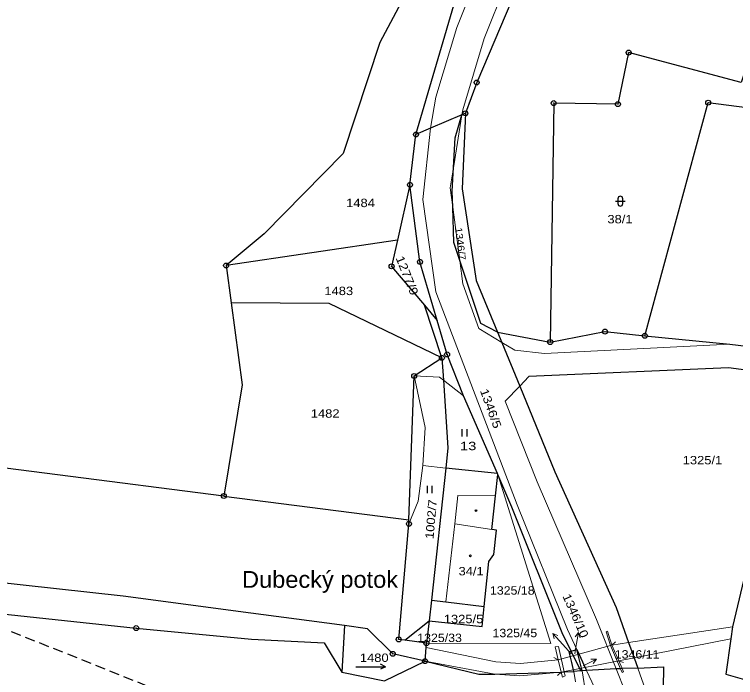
# Model space of a CAD drawing. Extents: x -872229 to -869198, y -1075981 to -1074329.
# Drawn here: x -871207 to -871061.1, y -1075218 to -1075083.8 of the extents above; entities that cross this region are included whole.
import ezdxf
from ezdxf.enums import TextEntityAlignment as Align

# ---------------------------------------------------------------- set-up
doc = ezdxf.new("R2010")
doc.units = 0
doc.header["$LTSCALE"] = 0.68
doc.linetypes.add('MEDIUM_DASHED', pattern=[4.5, 3, -1.5])
for name, color, linetype, lineweight in [('1', 7, 'Continuous', 25), ('3', 7, 'Continuous', 25), ('4', 7, 'Continuous', 13), ('5', 7, 'Continuous', 25), ('6', 7, 'Continuous', 25), ('7', 7, 'Continuous', 13), ('8', 7, 'Continuous', 25)]:
    doc.layers.add(name, color=color, linetype=linetype, lineweight=lineweight)
doc.layers.add('2', color=7, linetype='Continuous')

msp = doc.modelspace()

# ---------------------------------------------------------------- linework, layer by layer
at = {"layer": '1'}
for p, q in [((-871126.95, -1075118.28), (-871125.74, -1075108.09)), ((-871124.04, -1075142.67), (-871121.45, -1075145.75)), ((-871120.49, -1075153.3), (-871124.04, -1075142.67)), ((-871122.61, -1075202.33), (-871123.06, -1075206.55)), ((-871128.02, -1075210.46), (-871123.06, -1075206.55)), ((-871123.06, -1075206.55), (-871123.63, -1075211.06)), ((-871092.41, -1075216.68), (-871094.34, -1075212.69)), ((-871092.1, -1075216.66), (-871093.16, -1075212.36)), ((-871091.2, -1075216.61), (-871092.1, -1075216.66))]:
    msp.add_line(p, q, dxfattribs=at)
for points in [[(-871125.74, -1075108.09), (-871117.37, -1075079.56), (-871098, -1075028.09)], [(-871096.99, -1075058.79), (-871113.45, -1075097.58), (-871115.74, -1075103.81)], [(-871124.45, -1075073.24), (-871133.02, -1075089.5), (-871140.45, -1075111.97), (-871156.44, -1075128.18), (-871164.16, -1075134.61)], [(-871054.49, -1075088.37), (-871056.71, -1075087.82), (-871059.95, -1075097.6), (-871082.7, -1075091.52), (-871084.87, -1075101.96), (-871097.87, -1075101.74), (-871098.57, -1075150.11)], [(-871079.42, -1075148.83), (-871066.59, -1075101.65), (-871036.85, -1075105.44)], [(-871116.43, -1075104.1), (-871122.77, -1075106.82), (-871125.74, -1075108.09)], [(-871109.24, -1075148.09), (-871112.62, -1075146.34), (-871116.89, -1075133.59), (-871118.1, -1075129.96), (-871118.31, -1075122.79), (-871118.41, -1075119.59), (-871117.78, -1075108.8), (-871116.43, -1075104.1)], [(-871115.74, -1075103.81), (-871116.41, -1075104.1), (-871116.43, -1075104.1)], [(-871115.74, -1075103.81), (-871116.38, -1075119.08), (-871113.54, -1075137.64), (-871109.24, -1075148.09), (-871098.57, -1075150.11)], [(-871079.42, -1075148.83), (-871062.25, -1075150.52), (-871046.01, -1075152.47), (-871037.58, -1075154.42), (-871036.85, -1075105.44)], [(-871121.45, -1075145.75), (-871124.93, -1075133.89), (-871126.95, -1075118.28), (-871129.49, -1075129.5)], [(-871129.49, -1075129.5), (-871164.16, -1075134.61), (-871163.14, -1075142.16)], [(-871129.49, -1075129.5), (-871130.67, -1075134.78), (-871124.04, -1075142.67)], [(-871163.14, -1075142.16), (-871160.9, -1075158.75), (-871164.62, -1075181.27), (-871127.17, -1075186.06)], [(-871120.49, -1075153.3), (-871143.29, -1075142.31), (-871163.14, -1075142.16)], [(-871109.26, -1075176.73), (-871116.14, -1075160.96), (-871119.44, -1075152.61), (-871121.45, -1075145.75)], [(-871098.57, -1075150.11), (-871087.49, -1075147.99), (-871079.42, -1075148.83)], [(-871164.62, -1075181.27), (-871265.65, -1075168.37), (-871373.25, -1075154.62), (-871412.02, -1075149.67), (-871424.63, -1075148.05)], [(-871109.24, -1075148.09), (-871108.38, -1075150.17), (-871104.75, -1075159)], [(-871127.17, -1075186.06), (-871126.1, -1075156.97), (-871120.49, -1075153.3)], [(-871120.49, -1075153.3), (-871120.19, -1075157.85), (-871119.29, -1075171.49), (-871119.73, -1075175.61)], [(-870920.27, -1075200.54), (-870931.8, -1075197.32), (-870942.08, -1075192.95), (-870971.72, -1075177.36), (-871005.41, -1075167.04), (-871047.1, -1075157.35), (-871062.52, -1075155.35), (-871102.88, -1075157.06), (-871104.75, -1075159), (-871097.61, -1075176.34), (-871085.24, -1075203.86)], [(-871109.2, -1075176.94), (-871109.26, -1075176.73), (-871119.73, -1075175.61), (-871122.61, -1075202.33), (-871119.69, -1075202.71), (-871111.95, -1075203.66)], [(-871111.95, -1075203.66), (-871110.99, -1075194.53), (-871109.95, -1075193.13), (-871109.41, -1075188.17), (-871110.36, -1075188.06), (-871109.64, -1075181.21), (-871109.2, -1075176.94)], [(-871094.34, -1075212.69), (-871096.14, -1075208.96), (-871106.32, -1075183.51), (-871109.2, -1075176.94)], [(-871001.53, -1075179.18), (-871004.71, -1075177.87), (-871056.06, -1075184.2), (-871061.68, -1075207.72), (-871062.03, -1075210.19), (-871063.04, -1075217.35), (-871059.26, -1075218.39), (-871047.62, -1075220.14), (-871017.06, -1075226.57)], [(-871128.02, -1075210.46), (-871129.23, -1075210.29), (-871127.16, -1075186.91), (-871127.17, -1075186.06)], [(-871140.23, -1075207.5), (-871147.35, -1075206.55), (-871159.14, -1075204.95), (-871185.02, -1075201.57), (-871218.75, -1075197.81)], [(-871219.01, -1075204.11), (-871182.37, -1075208), (-871159.03, -1075210.24), (-871144.33, -1075210.97), (-871140.73, -1075216.95)], [(-871123.06, -1075206.55), (-871112.34, -1075207.69), (-871111.95, -1075203.66)], [(-871085.24, -1075203.86), (-871082.7, -1075210.94), (-871081.59, -1075214.04), (-871080.85, -1075216.08)], [(-871123.91, -1075214.69), (-871130.44, -1075213.21), (-871135.53, -1075208.13), (-871140.23, -1075207.5), (-871140.73, -1075216.95)], [(-871123.91, -1075214.69), (-871123.7, -1075211.96), (-871123.63, -1075211.06), (-871128.02, -1075210.46)], [(-871094.22, -1075214.97), (-871094.76, -1075212.8), (-871094.34, -1075212.69)], [(-871094.34, -1075212.69), (-871093.16, -1075212.36), (-871091.2, -1075216.61)], [(-871140.73, -1075216.95), (-871132.14, -1075218.66), (-871123.91, -1075214.69)], [(-871123.91, -1075214.69), (-871112.99, -1075217.35), (-871109.77, -1075217.3), (-871096.36, -1075216.91)], [(-871096.36, -1075216.91), (-871095.74, -1075216.87), (-871093.8, -1075216.76), (-871094.22, -1075214.97)], [(-871080.85, -1075216.08), (-871084.02, -1075216.21), (-871084.34, -1075216.22), (-871085.21, -1075216.27), (-871091.2, -1075216.61)], [(-871080.85, -1075216.08), (-871075.68, -1075215.86), (-871075.69, -1075220.23), (-871047.62, -1075220.14)], [(-871092.1, -1075216.66), (-871092.41, -1075216.68), (-871093.8, -1075216.76)]]:
    msp.add_lwpolyline(points, dxfattribs=at)
at = {"layer": '3'}
for p, q in [((-871085.391, -1075121.591), (-871083.389, -1075121.591)), ((-871084.891, -1075121.091), (-871084.891, -1075122.092)), ((-871083.889, -1075122.092), (-871083.889, -1075121.091)), ((-871116.411, -1075169.23), (-871116.411, -1075167.73)), ((-871115.41, -1075169.23), (-871115.41, -1075167.73)), ((-871123.431, -1075180.69), (-871123.431, -1075179.19)), ((-871122.43, -1075180.69), (-871122.43, -1075179.19)), ((-871131.933, -1075215.829), (-871132.91, -1075216.33))]:
    msp.add_line(p, q, dxfattribs=at)
msp.add_lwpolyline([(-871137.933, -1075215.829), (-871131.933, -1075215.829), (-871132.91, -1075215.327)], dxfattribs=at)
for centre, start, end in [((-871084.39, -1075121.0909), 0, 180), ((-871084.39, -1075122.0909), 180, 359.98789)]:
    msp.add_arc(centre, 0.5, start, end, dxfattribs=at)
at = {"layer": '4'}
for p, q in [((-871121.71, -1075100.52), (-871117.44, -1075086.44)), ((-871122.77, -1075106.82), (-871121.71, -1075100.52)), ((-871124.35, -1075121.24), (-871122.77, -1075106.82)), ((-871118.83, -1075118.87), (-871118.11, -1075114.44)), ((-871118.83, -1075118.87), (-871118.31, -1075122.79)), ((-871124.35, -1075121.24), (-871121.72, -1075139.93)), ((-871116.26, -1075138.33), (-871113.05, -1075147.37)), ((-871121.72, -1075139.93), (-871105.23, -1075183.06)), ((-871113.05, -1075147.37), (-871108.38, -1075150.17)), ((-871108.38, -1075150.17), (-871105.73, -1075151.76)), ((-871099.7, -1075152.44), (-871062.25, -1075150.52)), ((-871105.73, -1075151.76), (-871099.7, -1075152.44)), ((-871126.1, -1075156.97), (-871123.88, -1075167.38)), ((-871126.1, -1075156.97), (-871120.99, -1075157.24)), ((-871107.69, -1075162.06), (-871104.75, -1075159)), ((-871107.69, -1075162.06), (-871101.22, -1075178.38)), ((-871124.35, -1075175.12), (-871123.88, -1075167.38)), ((-871125.31, -1075182.31), (-871124.35, -1075175.12)), ((-871124.35, -1075175.12), (-871119.73, -1075175.61)), ((-871109.2, -1075176.94), (-871098.43, -1075211.1)), ((-871101.22, -1075178.38), (-871089.2, -1075206.25)), ((-871127.16, -1075186.91), (-871125.31, -1075182.31)), ((-871105.23, -1075183.06), (-871095.06, -1075208.25)), ((-871119.69, -1075202.71), (-871117.87, -1075186.88)), ((-871117.87, -1075186.88), (-871110.36, -1075188.06)), ((-871089.2, -1075206.25), (-871085.21, -1075216.27)), ((-871082.7, -1075210.94), (-871061.68, -1075207.72)), ((-871095.06, -1075208.25), (-871093.16, -1075212.36)), ((-871087.28, -1075208.73), (-871086.99, -1075208.64)), ((-871087.28, -1075208.73), (-871086.38, -1075211.55)), ((-871086.99, -1075208.64), (-871086.09, -1075211.46)), ((-871085.382, -1075210.753), (-871086.089, -1075211.46)), ((-871081.59, -1075214.04), (-871062.03, -1075210.19)), ((-871123.7, -1075211.96), (-871109.59, -1075214.81)), ((-871123.63, -1075211.06), (-871098.43, -1075211.1)), ((-871097.55, -1075211.81), (-871096.93, -1075211.74)), ((-871096.93, -1075211.74), (-871095.74, -1075216.87)), ((-871086.38, -1075211.55), (-871084.34, -1075216.22)), ((-871086.09, -1075211.46), (-871082.7, -1075210.94)), ((-871086.09, -1075211.46), (-871084.69, -1075214.65)), ((-871123.91, -1075214.69), (-871109.77, -1075217.3)), ((-871109.59, -1075214.81), (-871104.57, -1075215.17)), ((-871104.57, -1075215.17), (-871096.95, -1075214.41)), ((-871097.841, -1075213.955), (-871096.95, -1075214.409)), ((-871096.36, -1075216.91), (-871084.69, -1075214.65)), ((-871084.69, -1075214.65), (-871081.59, -1075214.04)), ((-871084.69, -1075214.65), (-871084.02, -1075216.21)), ((-871083.739, -1075214.96), (-871084.69, -1075214.651)), ((-871091.2, -1075216.61), (-871089.08, -1075221.2)), ((-871085.21, -1075216.27), (-871083.4, -1075220.8)), ((-871084.34, -1075216.22), (-871084.02, -1075216.96)), ((-871084.02, -1075216.21), (-871083.74, -1075216.84)), ((-871080.85, -1075216.08), (-871079.27, -1075220.49)), ((-871109.77, -1075217.3), (-871104.75, -1075217.66)), ((-871104.75, -1075217.66), (-871096.36, -1075216.91)), ((-871097.068, -1075217.617), (-871096.361, -1075216.91)), ((-871095.74, -1075216.87), (-871095.56, -1075217.65)), ((-871093.8, -1075216.76), (-871093.43, -1075218.88)), ((-871092.1, -1075216.66), (-871091.39, -1075221.36)), ((-871084.02, -1075216.96), (-871083.74, -1075216.84))]:
    msp.add_line(p, q, dxfattribs=at)
for points in [[(-871117.44, -1075086.44), (-871104.3, -1075053.55), (-871091.42, -1075021.56)], [(-871098.77, -1075055.79), (-871111.92, -1075088.68), (-871116.26, -1075103.1)], [(-871118.11, -1075114.44), (-871116.43, -1075104.1), (-871116.26, -1075103.1)], [(-871118.31, -1075122.79), (-871116.89, -1075133.59), (-871116.26, -1075138.33)], [(-871120.99, -1075157.24), (-871120.19, -1075157.85), (-871116.14, -1075160.96)], [(-871117.87, -1075186.88), (-871117.29, -1075181.19), (-871109.64, -1075181.21)], [(-871097.55, -1075211.81), (-871096.95, -1075214.41), (-871096.36, -1075216.91)], [(-871096.95, -1075214.41), (-871086.38, -1075211.55), (-871086.09, -1075211.46)], [(-871096.36, -1075216.91), (-871096.07, -1075217.9), (-871095.56, -1075217.65)]]:
    msp.add_lwpolyline(points, dxfattribs=at)
at = {"layer": '5'}
for centre in [(-871113.5868, -1075184.2092), (-871114.7368, -1075193.3692)]:
    msp.add_circle(centre, 0.175, dxfattribs=at)
at = {"layer": '6', "linetype": 'MEDIUM_DASHED'}
msp.add_line((-871219.01, -1075204.11), (-871164.94, -1075225.78), dxfattribs=at)
at = {"layer": '7'}
for p, q in [((-871098.048, -1075209.1), (-871097.75, -1075210.179)), ((-871092.839, -1075208.875), (-871093.506, -1075209.774)), ((-871089.236, -1075214.258), (-871090.356, -1075214.266))]:
    msp.add_line(p, q, dxfattribs=at)
for points in [[(-871094.36, -1075213.18), (-871096.04, -1075211.33), (-871098.048, -1075209.1), (-871097.006, -1075209.509)], [(-871093.61, -1075213.2), (-871093.36, -1075211.83), (-871092.839, -1075208.875), (-871092.52, -1075209.948)], [(-871091.91, -1075215.62), (-871089.236, -1075214.258), (-871089.901, -1075215.158)]]:
    msp.add_lwpolyline(points, dxfattribs=at)
at = {"layer": '8'}
for centre, radius in [((-871082.7, -1075091.5199), 0.5), ((-871082.7, -1075091.5199), 0.0303), ((-871113.45, -1075097.5799), 0.5), ((-871113.45, -1075097.5799), 0.0303), ((-871097.87, -1075101.7399), 0.5), ((-871066.59, -1075101.6499), 0.5), ((-871097.87, -1075101.7399), 0.0303), ((-871084.87, -1075101.9599), 0.5), ((-871084.87, -1075101.9599), 0.0303), ((-871066.59, -1075101.6499), 0.0303), ((-871115.74, -1075103.8099), 0.5), ((-871115.74, -1075103.8099), 0.0303), ((-871125.74, -1075108.0899), 0.5), ((-871125.74, -1075108.0899), 0.0303), ((-871126.95, -1075118.2799), 0.5), ((-871126.95, -1075118.2799), 0.0303), ((-871124.93, -1075133.8899), 0.5), ((-871164.16, -1075134.6099), 0.5), ((-871164.16, -1075134.6099), 0.0303), ((-871130.67, -1075134.7799), 0.5), ((-871130.67, -1075134.7799), 0.0303), ((-871124.93, -1075133.8899), 0.0303), ((-871087.49, -1075147.9899), 0.5), ((-871087.49, -1075147.9899), 0.0303), ((-871079.42, -1075148.8299), 0.5), ((-871079.42, -1075148.8299), 0.0303), ((-871098.57, -1075150.1099), 0.5), ((-871098.57, -1075150.1099), 0.0303), ((-871119.44, -1075152.6099), 0.5), ((-871120.49, -1075153.2999), 0.5), ((-871120.49, -1075153.2999), 0.0303), ((-871119.44, -1075152.6099), 0.0303), ((-871126.1, -1075156.9699), 0.5), ((-871126.1, -1075156.9699), 0.0303), ((-871164.62, -1075181.2699), 0.5), ((-871164.62, -1075181.2699), 0.0303), ((-871127.16, -1075186.9099), 0.5), ((-871127.16, -1075186.9099), 0.0303), ((-871182.37, -1075207.9999), 0.5), ((-871182.37, -1075207.9999), 0.0303), ((-871129.23, -1075210.2899), 0.5), ((-871129.23, -1075210.2899), 0.0303), ((-871123.63, -1075211.0599), 0.5), ((-871123.63, -1075211.0599), 0.0303), ((-871130.44, -1075213.2099), 0.5), ((-871130.44, -1075213.2099), 0.0303), ((-871123.91, -1075214.6899), 0.5), ((-871123.91, -1075214.6899), 0.0303)]:
    msp.add_circle(centre, radius, dxfattribs=at)

# ---------------------------------------------------------------- texts
at = {"layer": '2'}
for s, width, p in [('1484', 1.15, (-871139.87, -1075122.79)), ('38/1', 1.15, (-871087, -1075126.08)), ('1483', 1.15, (-871144.27, -1075140.6)), ('1482', 1.15, (-871147.02, -1075165.42)), ('13', 1.3, (-871116.82, -1075171.99)), ('1325/1', 1.15, (-871071.76, -1075174.86)), ('34/1', 1.15, (-871117.13, -1075197.33)), ('1325/18', 1.1, (-871110.77, -1075201.23)), ('1325/5', 1.15, (-871120.11, -1075207.01)), ('1325/33', 1.1, (-871125.48, -1075210.82)), ('1480', 1.15, (-871137.09, -1075214.85))]:
    msp.add_text(s, height=1.7, dxfattribs=dict(at, width=width)).set_placement(p)
at = {"layer": '2', "width": 1.15}
for s, height, rotation, p in [('1346/7', 1.418, 277, (-871117.4465, -1075130.2946)), ('1346/10', 1.7, 294, (-871094.2124, -1075205.8388))]:
    msp.add_text(s, height=height, rotation=rotation, dxfattribs=at).set_placement(p, align=Align.CENTER)
at = {"layer": '2'}
for s, rotation, width, p in [('1277/9', 292, 1.2, (-871129.878, -1075133.088)), ('1346/5', 290, 1.2, (-871112.818, -1075159.92)), ('1002/7', 85, 1.15, (-871122.193, -1075190.024))]:
    msp.add_text(s, height=1.7, rotation=rotation, dxfattribs=dict(at, width=width)).set_placement(p)
at = {"layer": '2', "width": 1.1}
for s, p in [('1325/45', (-871105.729, -1075209.84)), ('1346/11', (-871080.989, -1075214.17))]:
    msp.add_text(s, height=1.7, dxfattribs=at).set_placement(p, align=Align.CENTER)
at = {"layer": '7', "width": 1.05}
msp.add_text('Dubecký potok', height=3.4, dxfattribs=at).set_placement((-871160.94, -1075199.85))

doc.saveas('drawing.dxf')
